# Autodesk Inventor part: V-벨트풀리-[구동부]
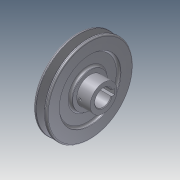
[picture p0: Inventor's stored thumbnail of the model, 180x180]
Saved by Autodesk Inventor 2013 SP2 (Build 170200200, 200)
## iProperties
Company: 한국ATC센터
Created: 2014-10
Part Number: V-벨트풀리-[구동부]
Document SubType Name: Modeling
Designer: 한국ATC센터
Density: 7.86 g/cm^3
Material: 강, 연강
Mass: 1515.01 g
Surface Area: 468.125 cm^2
Volume: 192.75 cm^3
Author: KYOUNG IL JANG
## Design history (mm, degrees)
sketch "스케치1"
  geometry: L1 (-20, 0)-(20, 0); L2 (-20, 0)-(-20, 26); L3 (-20, 26)-(-16, 26); L4 (-16, 26)-(-16, 46); L5 (-16, 46)-(-20, 46); L6 (-20, 46)-(-20, 64.5); L7 (-20, 64.5)-(-16.062, 64.5); L8 (-16.062, 64.5)-(-12.001, 52); L9 (-12.001, 52)-(-7.999, 52); L10 (-7.999, 52)-(-3.938, 64.5); L11 (-3.938, 64.5)-(0, 64.5); L12 (0, 64.5)-(0, 46); L13 (0, 46)-(-4, 46); L14 (-4, 46)-(-4, 26); L15 (-4, 26)-(0, 26); L16 (0, 26)-(0, 20); L17 (0, 20)-(20, 20); L18 (20, 20)-(20, 0); L19 (-14.6, 60)-(-5.4, 60); 2 further points
  constraints: 38 end point, 11 parallel, 7 collinear, 3 equal length, 3 perpendicular, 2 point on line, 1 coincident, 1 horizontal, 1 midpoint
  dimensions: "d0" = 40 distance of L1.start L1.end; "d1" = 4.5 distance between parallel lines of L7 L19; "d2" = 8 distance between parallel lines of L9 L19; "d3" = 9.2 distance of L19.start L19.end; "d4" = 36 deg angle of L10 L8; "d5" = 20 distance between parallel lines of L12 L6; "d6" = 120 diameter of L19 L1; "d7" = 4 distance of L2.end L3.end; "d8" = 52 diameter of L3 L1; "d9" = 92 diameter of L5 L1; "d10" = 40 diameter of L17 L1
revolve "회전1" sketch "스케치1" stored, may be unused: angle "d11" = 90 deg
sketch "스케치2"
  geometry: L1 (-4, 11.843)-(-4, 16.5); L2 (-4, 16.5)-(4, 16.5); L3 (4, 16.5)-(4, 11.843); A1 r 12.5 centre (0, 0) between (-4, 11.843) and (4, 11.843); 1 further point
  constraints: 6 end point, 2 parallel, 2 point on circle, 1 centre point, 1 coincident, 1 horizontal, 1 vertical
  dimensions: "d12" = 25 diameter of A1; "d13" = 8 distance of L1.end L2.end; "d14" = 29 dimension on A1 L2
extrude "돌출1" cut sketch "스케치2" stored distance "d15" = 10; taper "d16" = 0 deg
chamfer "모따기1" distance "d17" = 1; stored, may be unused: second distance "d18" = 2, angle "d19" = 45 deg
node "작업 평면1"
sketch "스케치3"
  geometry: L1 (10, -20)-(10, 20) reference; 3 further points
  constraints: 1 horizontal alignment, 1 midpoint
  dimensions: "d20" = 15 distance from line of L1 point (-5, 0)
hole "구멍1" sketch "스케치3" at (-5, 0) diameter "d21" = 4.459; stored, may be unused: countersink angle "d25" = 90 deg, drill point angle "d27" = 118 deg; dims "d22" = 6, "d23" = 4, "d24" = 2, "d26" = 8
fillet "모깎기1" dims "d28" = 3, "d29" = 2, "d30" = 0.5, "d31" = 1
node "솔리드1"
